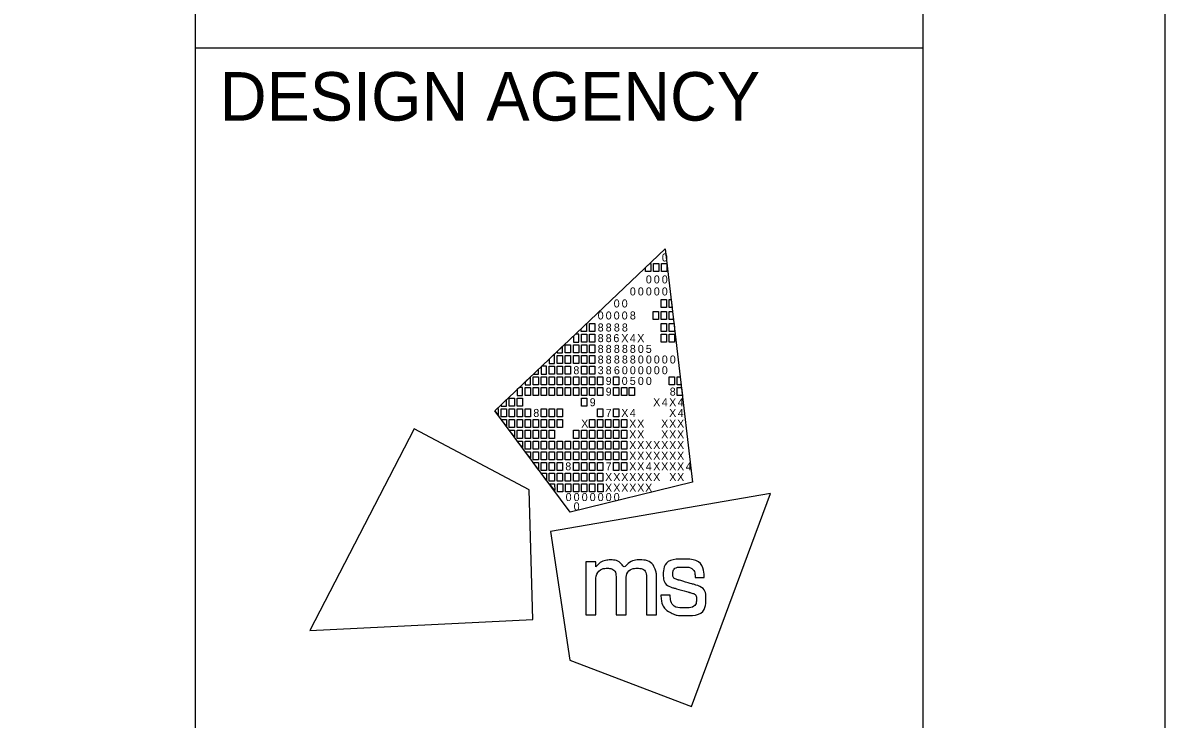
# Model space of a CAD drawing. Extents: x 0 to 34, y 0 to 22.
# Drawn here: x 31.644 to 34, y 3.616 to 5.052 of the extents above; entities that cross this region are included whole.
import ezdxf

# ---------------------------------------------------------------- set-up
doc = ezdxf.new("R2010")
doc.units = 0
for name, color, linetype in [('SH_Border', 7, 'Continuous'), ('SH_Cut_Line', 7, 'Continuous'), ('SH_Data', 7, 'Continuous')]:
    doc.layers.add(name, color=color, linetype=linetype)

msp = doc.modelspace()

# ---------------------------------------------------------------- linework, layer by layer
at = {"layer": 'SH_Border'}
for p, q in [((32, 0.5), (32, 21.5)), ((32, 5), (33.5, 5)), ((32.6175, 4.2519), (32.9688, 4.5861)), ((32.9688, 4.5861), (32.9688, 4.5861)), ((32.9688, 4.5861), (33.0253, 4.1052)), ((32.773, 4.043), (32.6175, 4.2519)), ((33.0253, 4.1052), (32.773, 4.043))]:
    msp.add_line(p, q, dxfattribs=at)
for points in [[(1.5, 21.5), (33.5, 21.5), (33.5, 0.5), (1.5, 0.5)], [(32.9279, 4.5472), (32.9369, 4.5558), (32.9389, 4.5558), (32.9389, 4.5393), (32.9279, 4.5393)], [(32.9444, 4.5558), (32.9554, 4.5558), (32.9554, 4.5393), (32.9444, 4.5393)], [(32.9609, 4.5558), (32.9719, 4.5558), (32.9719, 4.5393), (32.9609, 4.5393)], [(32.9606, 4.4815), (32.9716, 4.4815), (32.9716, 4.465), (32.9606, 4.465)], [(32.9771, 4.4815), (32.9811, 4.4815), (32.983, 4.465), (32.9771, 4.465)], [(32.9441, 4.4567), (32.9551, 4.4567), (32.9551, 4.4402), (32.9441, 4.4402)], [(32.9606, 4.4567), (32.9716, 4.4567), (32.9716, 4.4402), (32.9606, 4.4402)], [(32.9771, 4.4567), (32.984, 4.4567), (32.9859, 4.4402), (32.9771, 4.4402)], [(32.7953, 4.4211), (32.8064, 4.4316), (32.8064, 4.4154), (32.7953, 4.4154)], [(32.8123, 4.4319), (32.8233, 4.4319), (32.8233, 4.4154), (32.8123, 4.4154)], [(32.9606, 4.4319), (32.9716, 4.4319), (32.9716, 4.4154), (32.9606, 4.4154)], [(32.9771, 4.4319), (32.9869, 4.4319), (32.9881, 4.4218), (32.9881, 4.4154), (32.9771, 4.4154)], [(32.7958, 4.4099), (32.8068, 4.4099), (32.8068, 4.3934), (32.7958, 4.3934)], [(32.8123, 4.4099), (32.8233, 4.4099), (32.8233, 4.3934), (32.8123, 4.3934)], [(32.9606, 4.4099), (32.9716, 4.4099), (32.9716, 4.3934), (32.9606, 4.3934)], [(32.9771, 4.4099), (32.9881, 4.4099), (32.9881, 4.3934), (32.9771, 4.3934)], [(32.7627, 4.3879), (32.7737, 4.3879), (32.7737, 4.3714), (32.7627, 4.3714)], [(32.7793, 4.3879), (32.7903, 4.3879), (32.7903, 4.3714), (32.7793, 4.3714)], [(32.7958, 4.3879), (32.8068, 4.3879), (32.8068, 4.3714), (32.7958, 4.3714)], [(32.8123, 4.3879), (32.8233, 4.3879), (32.8233, 4.3714), (32.8123, 4.3714)], [(32.7462, 4.3659), (32.7572, 4.3659), (32.7572, 4.3494), (32.7462, 4.3494)], [(32.7627, 4.3659), (32.7737, 4.3659), (32.7737, 4.3494), (32.7627, 4.3494)], [(32.7793, 4.3659), (32.7903, 4.3659), (32.7903, 4.3494), (32.7793, 4.3494)], [(32.7958, 4.3659), (32.8068, 4.3659), (32.8068, 4.3494), (32.7958, 4.3494)], [(32.8123, 4.3659), (32.8233, 4.3659), (32.8233, 4.3494), (32.8123, 4.3494)], [(32.7297, 4.3439), (32.7407, 4.3439), (32.7407, 4.3273), (32.7297, 4.3273)], [(32.7462, 4.3439), (32.7572, 4.3439), (32.7572, 4.3273), (32.7462, 4.3273)], [(32.7627, 4.3439), (32.7737, 4.3439), (32.7737, 4.3273), (32.7627, 4.3273)], [(32.7958, 4.3439), (32.8068, 4.3439), (32.8068, 4.3273), (32.7958, 4.3273)], [(32.8123, 4.3439), (32.8233, 4.3439), (32.8233, 4.3273), (32.8123, 4.3273)], [(32.6967, 4.3218), (32.7077, 4.3218), (32.7077, 4.3053), (32.6967, 4.3053)], [(32.7132, 4.3218), (32.7242, 4.3218), (32.7242, 4.3053), (32.7132, 4.3053)], [(32.7297, 4.3218), (32.7407, 4.3218), (32.7407, 4.3053), (32.7297, 4.3053)], [(32.7462, 4.3218), (32.7572, 4.3218), (32.7572, 4.3053), (32.7462, 4.3053)], [(32.7627, 4.3218), (32.7737, 4.3218), (32.7737, 4.3053), (32.7627, 4.3053)], [(32.7793, 4.3218), (32.7903, 4.3218), (32.7903, 4.3053), (32.7793, 4.3053)], [(32.7958, 4.3218), (32.8068, 4.3218), (32.8068, 4.3053), (32.7958, 4.3053)], [(32.8123, 4.3218), (32.8233, 4.3218), (32.8233, 4.3053), (32.8123, 4.3053)], [(32.8288, 4.3218), (32.8398, 4.3218), (32.8398, 4.3053), (32.8288, 4.3053)], [(32.8618, 4.3218), (32.8728, 4.3218), (32.8728, 4.3053), (32.8618, 4.3053)], [(32.9771, 4.3218), (32.9881, 4.3218), (32.9881, 4.3053), (32.9771, 4.3053)], [(32.9935, 4.3218), (32.9998, 4.3218), (33.0018, 4.3053), (32.9935, 4.3053)], [(32.6802, 4.2998), (32.6912, 4.2998), (32.6912, 4.2833), (32.6802, 4.2833)], [(32.6967, 4.2998), (32.7077, 4.2998), (32.7077, 4.2833), (32.6967, 4.2833)], [(32.7132, 4.2998), (32.7242, 4.2998), (32.7242, 4.2833), (32.7132, 4.2833)], [(32.7297, 4.2998), (32.7407, 4.2998), (32.7407, 4.2833), (32.7297, 4.2833)], [(32.7462, 4.2998), (32.7572, 4.2998), (32.7572, 4.2833), (32.7462, 4.2833)], [(32.7627, 4.2998), (32.7737, 4.2998), (32.7737, 4.2833), (32.7627, 4.2833)], [(32.7793, 4.2998), (32.7903, 4.2998), (32.7903, 4.2833), (32.7793, 4.2833)], [(32.7958, 4.2998), (32.8068, 4.2998), (32.8068, 4.2833), (32.7958, 4.2833)], [(32.8123, 4.2998), (32.8233, 4.2998), (32.8233, 4.2833), (32.8123, 4.2833)], [(32.8288, 4.2998), (32.8398, 4.2998), (32.8398, 4.2833), (32.8288, 4.2833)], [(32.8618, 4.2998), (32.8728, 4.2998), (32.8728, 4.2833), (32.8618, 4.2833)], [(32.8783, 4.2998), (32.8893, 4.2998), (32.8893, 4.2833), (32.8783, 4.2833)], [(32.8947, 4.2998), (32.9057, 4.2998), (32.9057, 4.2833), (32.8947, 4.2833)], [(32.9935, 4.2998), (33.0024, 4.2998), (33.0044, 4.2833), (32.9935, 4.2833)], [(32.6471, 4.2778), (32.6581, 4.2778), (32.6581, 4.2613), (32.6471, 4.2613)], [(32.6637, 4.2778), (32.6747, 4.2778), (32.6747, 4.2613), (32.6637, 4.2613)], [(32.7958, 4.2778), (32.8068, 4.2778), (32.8068, 4.2613), (32.7958, 4.2613)], [(32.6306, 4.2558), (32.6416, 4.2558), (32.6416, 4.2393), (32.6306, 4.2393)], [(32.6471, 4.2558), (32.6581, 4.2558), (32.6581, 4.2393), (32.6471, 4.2393)], [(32.6637, 4.2558), (32.6747, 4.2558), (32.6747, 4.2393), (32.6637, 4.2393)], [(32.6802, 4.2558), (32.6912, 4.2558), (32.6912, 4.2393), (32.6802, 4.2393)], [(32.7132, 4.2558), (32.7242, 4.2558), (32.7242, 4.2393), (32.7132, 4.2393)], [(32.7297, 4.2558), (32.7407, 4.2558), (32.7407, 4.2393), (32.7297, 4.2393)], [(32.7462, 4.2558), (32.7572, 4.2558), (32.7572, 4.2393), (32.7462, 4.2393)], [(32.8288, 4.2558), (32.8398, 4.2558), (32.8398, 4.2393), (32.8288, 4.2393)], [(32.8618, 4.2558), (32.8728, 4.2558), (32.8728, 4.2393), (32.8618, 4.2393)], [(32.6306, 4.2338), (32.6416, 4.2338), (32.6416, 4.22)], [(32.6471, 4.2338), (32.6581, 4.2338), (32.6581, 4.2173), (32.6471, 4.2173)], [(32.6637, 4.2338), (32.6747, 4.2338), (32.6747, 4.2173), (32.6637, 4.2173)], [(32.6802, 4.2338), (32.6912, 4.2338), (32.6912, 4.2173), (32.6802, 4.2173)], [(32.6967, 4.2338), (32.7077, 4.2338), (32.7077, 4.2173), (32.6967, 4.2173)], [(32.7132, 4.2338), (32.7242, 4.2338), (32.7242, 4.2173), (32.7132, 4.2173)], [(32.7297, 4.2338), (32.7407, 4.2338), (32.7407, 4.2173), (32.7297, 4.2173)], [(32.7462, 4.2338), (32.7572, 4.2338), (32.7572, 4.2173), (32.7462, 4.2173)], [(32.8123, 4.2338), (32.8233, 4.2338), (32.8233, 4.2173), (32.8123, 4.2173)], [(32.8288, 4.2338), (32.8398, 4.2338), (32.8398, 4.2173), (32.8288, 4.2173)], [(32.8453, 4.2338), (32.8563, 4.2338), (32.8563, 4.2173), (32.8453, 4.2173)], [(32.8618, 4.2338), (32.8728, 4.2338), (32.8728, 4.2173), (32.8618, 4.2173)], [(32.8783, 4.2338), (32.8893, 4.2338), (32.8893, 4.2173), (32.8783, 4.2173)], [(32.6471, 4.2117), (32.6581, 4.2117), (32.6581, 4.198)], [(32.6637, 4.2117), (32.6747, 4.2117), (32.6747, 4.1952), (32.6637, 4.1952)], [(32.6802, 4.2117), (32.6912, 4.2117), (32.6912, 4.1952), (32.6802, 4.1952)], [(32.6967, 4.2117), (32.7077, 4.2117), (32.7077, 4.1952), (32.6967, 4.1952)], [(32.7132, 4.2117), (32.7242, 4.2117), (32.7242, 4.1952), (32.7132, 4.1952)], [(32.7297, 4.2117), (32.7407, 4.2117), (32.7407, 4.1952), (32.7297, 4.1952)], [(32.7793, 4.2117), (32.7903, 4.2117), (32.7903, 4.1952), (32.7793, 4.1952)], [(32.7958, 4.2117), (32.8068, 4.2117), (32.8068, 4.1952), (32.7958, 4.1952)], [(32.8123, 4.2117), (32.8233, 4.2117), (32.8233, 4.1952), (32.8123, 4.1952)], [(32.8288, 4.2117), (32.8398, 4.2117), (32.8398, 4.1952), (32.8288, 4.1952)], [(32.8453, 4.2117), (32.8563, 4.2117), (32.8563, 4.1952), (32.8453, 4.1952)], [(32.8618, 4.2117), (32.8728, 4.2117), (32.8728, 4.1952), (32.8618, 4.1952)], [(32.8783, 4.2117), (32.8893, 4.2117), (32.8893, 4.1952), (32.8783, 4.1952)], [(32.6637, 4.1897), (32.6747, 4.1897), (32.6747, 4.176)], [(32.6747, 4.1897), (32.6747, 4.1897), (32.6747, 4.1897)], [(32.6802, 4.1897), (32.6912, 4.1897), (32.6912, 4.1732), (32.6802, 4.1732)], [(32.6967, 4.1897), (32.7077, 4.1897), (32.7077, 4.1732), (32.6967, 4.1732)], [(32.7132, 4.1897), (32.7242, 4.1897), (32.7242, 4.1732), (32.7132, 4.1732)], [(32.7297, 4.1897), (32.7407, 4.1897), (32.7407, 4.1732), (32.7297, 4.1732)], [(32.7462, 4.1897), (32.7572, 4.1897), (32.7572, 4.1732), (32.7462, 4.1732)], [(32.7627, 4.1897), (32.7737, 4.1897), (32.7737, 4.1732), (32.7627, 4.1732)], [(32.7793, 4.1897), (32.7903, 4.1897), (32.7903, 4.1732), (32.7793, 4.1732)], [(32.7958, 4.1897), (32.8068, 4.1897), (32.8068, 4.1732), (32.7958, 4.1732)], [(32.8123, 4.1897), (32.8233, 4.1897), (32.8233, 4.1732), (32.8123, 4.1732)], [(32.8288, 4.1897), (32.8398, 4.1897), (32.8398, 4.1732), (32.8288, 4.1732)], [(32.8453, 4.1897), (32.8563, 4.1897), (32.8563, 4.1732), (32.8453, 4.1732)], [(32.8618, 4.1897), (32.8728, 4.1897), (32.8728, 4.1732), (32.8618, 4.1732)], [(32.8783, 4.1897), (32.8893, 4.1897), (32.8893, 4.1732), (32.8783, 4.1732)], [(32.6802, 4.1677), (32.6912, 4.1677), (32.6912, 4.154)], [(32.6967, 4.1677), (32.7077, 4.1677), (32.7077, 4.1512), (32.6967, 4.1512)], [(32.7132, 4.1677), (32.7242, 4.1677), (32.7242, 4.1512), (32.7132, 4.1512)], [(32.7297, 4.1677), (32.7407, 4.1677), (32.7407, 4.1512), (32.7297, 4.1512)], [(32.7462, 4.1677), (32.7572, 4.1677), (32.7572, 4.1512), (32.7462, 4.1512)], [(32.7627, 4.1677), (32.7737, 4.1677), (32.7737, 4.1512), (32.7627, 4.1512)], [(32.7793, 4.1677), (32.7903, 4.1677), (32.7903, 4.1512), (32.7793, 4.1512)], [(32.7958, 4.1677), (32.8068, 4.1677), (32.8068, 4.1512), (32.7958, 4.1512)], [(32.8123, 4.1677), (32.8233, 4.1677), (32.8233, 4.1512), (32.8123, 4.1512)], [(32.8288, 4.1677), (32.8398, 4.1677), (32.8398, 4.1512), (32.8288, 4.1512)], [(32.8453, 4.1677), (32.8563, 4.1677), (32.8563, 4.1512), (32.8453, 4.1512)], [(32.8618, 4.1677), (32.8728, 4.1677), (32.8728, 4.1512), (32.8618, 4.1512)], [(32.8783, 4.1677), (32.8893, 4.1677), (32.8893, 4.1512), (32.8783, 4.1512)], [(32.7077, 4.1305), (32.6965, 4.1457), (32.7077, 4.1457)], [(32.7132, 4.1457), (32.7242, 4.1457), (32.7242, 4.1292), (32.7132, 4.1292)], [(32.724, 4.1082), (32.7132, 4.1237), (32.7242, 4.1237)], [(32.7297, 4.1457), (32.7407, 4.1457), (32.7407, 4.1292), (32.7297, 4.1292)], [(32.7297, 4.1237), (32.7407, 4.1237), (32.7407, 4.1072), (32.7297, 4.1072)], [(32.7462, 4.1457), (32.7572, 4.1457), (32.7572, 4.1292), (32.7462, 4.1292)], [(32.7462, 4.1237), (32.7572, 4.1237), (32.7572, 4.1072), (32.7462, 4.1072)], [(32.7627, 4.1237), (32.7737, 4.1237), (32.7737, 4.1072), (32.7627, 4.1072)], [(32.7793, 4.1457), (32.7903, 4.1457), (32.7903, 4.1292), (32.7793, 4.1292)], [(32.7793, 4.1237), (32.7903, 4.1237), (32.7903, 4.1072), (32.7793, 4.1072)], [(32.7958, 4.1457), (32.8068, 4.1457), (32.8068, 4.1292), (32.7958, 4.1292)], [(32.7958, 4.1237), (32.8068, 4.1237), (32.8068, 4.1072), (32.7958, 4.1072)], [(32.8123, 4.1457), (32.8233, 4.1457), (32.8233, 4.1292), (32.8123, 4.1292)], [(32.8123, 4.1237), (32.8233, 4.1237), (32.8233, 4.1072), (32.8123, 4.1072)], [(32.8288, 4.1457), (32.8398, 4.1457), (32.8398, 4.1292), (32.8288, 4.1292)], [(32.8288, 4.1237), (32.8398, 4.1237), (32.8398, 4.1072), (32.8288, 4.1072)], [(32.8618, 4.1457), (32.8728, 4.1457), (32.8728, 4.1292), (32.8618, 4.1292)], [(32.8783, 4.1457), (32.8893, 4.1457), (32.8893, 4.1292), (32.8783, 4.1292)], [(32.7302, 4.1017), (32.7407, 4.1017), (32.7408, 4.0875)], [(32.7463, 4.1017), (32.7573, 4.1017), (32.7573, 4.0852), (32.7463, 4.0852)], [(32.763, 4.1017), (32.774, 4.1017), (32.774, 4.0852), (32.763, 4.0852)], [(32.7794, 4.1017), (32.7904, 4.1017), (32.7904, 4.0852), (32.7794, 4.0852)], [(32.796, 4.1017), (32.807, 4.1017), (32.807, 4.0852), (32.796, 4.0852)], [(32.8129, 4.1017), (32.8239, 4.1017), (32.8239, 4.0851), (32.8129, 4.0851)], [(32.8296, 4.1017), (32.8406, 4.1017), (32.8406, 4.0851), (32.8296, 4.0851)]]:
    msp.add_lwpolyline(points, close=True, dxfattribs=at)
for points in [[(32.7903, 4.4099), (32.7836, 4.4099), (32.7793, 4.4058), (32.7793, 4.3934), (32.7903, 4.3934), (32.7903, 4.4099)], [(32.7572, 4.3849), (32.7462, 4.3744), (32.7462, 4.3714), (32.7572, 4.3714), (32.7572, 4.3849)], [(32.7407, 4.3691), (32.7297, 4.3587), (32.7297, 4.3494), (32.7407, 4.3494), (32.7407, 4.3691)], [(32.7077, 4.3377), (32.6968, 4.3273), (32.7077, 4.3273), (32.7077, 4.3377)], [(32.7242, 4.3439), (32.7141, 4.3439), (32.7132, 4.343), (32.7132, 4.3273), (32.7242, 4.3273), (32.7242, 4.3439)], [(32.6912, 4.322), (32.6802, 4.3115), (32.6802, 4.3053), (32.6912, 4.3053), (32.6912, 4.322)], [(32.6747, 4.2998), (32.6679, 4.2998), (32.6637, 4.2958), (32.6637, 4.2833), (32.6747, 4.2833), (32.6747, 4.2998)], [(32.6416, 4.2749), (32.6306, 4.2644), (32.6306, 4.2613), (32.6416, 4.2613), (32.6416, 4.2749)], [(32.6251, 4.2558), (32.6216, 4.2558), (32.6175, 4.2519), (32.6251, 4.2417), (32.6251, 4.2558)], [(32.4512, 4.2149), (32.2359, 3.7988), (32.6956, 3.8215), (32.6884, 4.0892), (32.4512, 4.2149)], [(33.0229, 3.6422), (33.1859, 4.0814), (32.7324, 4.0029), (32.7722, 3.7381), (33.0229, 3.6422)]]:
    msp.add_lwpolyline(points, dxfattribs=at)
for points in [[(32.8048, 3.8315), (32.8048, 3.8315), (32.8048, 3.9409), (32.8048, 3.9409), (32.8048, 3.9409), (32.8255, 3.9409), (32.8255, 3.9409), (32.8255, 3.9409), (32.8255, 3.9297), (32.8255, 3.9297), (32.8346, 3.9399), (32.8457, 3.9445), (32.8555, 3.9445), (32.8688, 3.9445), (32.8791, 3.9372), (32.8837, 3.9266), (32.8915, 3.9381), (32.905, 3.9446), (32.9166, 3.9446), (32.9325, 3.9446), (32.9451, 3.935), (32.9494, 3.9213), (32.9494, 3.9212), (32.9494, 3.9212), (32.9494, 3.9212), (32.9501, 3.919), (32.9506, 3.9172), (32.9506, 3.9071), (32.9506, 3.9071), (32.9506, 3.8314), (32.9506, 3.8314), (32.9506, 3.8314), (32.9303, 3.8314), (32.9303, 3.8314), (32.9303, 3.8314), (32.9303, 3.9048), (32.9303, 3.9048), (32.9303, 3.9201), (32.9219, 3.9274), (32.911, 3.9274), (32.8995, 3.9274), (32.8879, 3.9171), (32.8879, 3.9001), (32.8879, 3.9001), (32.8879, 3.8315), (32.8879, 3.8315), (32.8879, 3.8315), (32.8674, 3.8315), (32.8674, 3.8315), (32.8674, 3.8315), (32.8674, 3.9059), (32.8674, 3.9059), (32.8674, 3.9203), (32.8588, 3.9274), (32.8496, 3.9274), (32.8384, 3.9274), (32.8254, 3.917), (32.8254, 3.8962), (32.8254, 3.8962), (32.8254, 3.8315), (32.8254, 3.8315), (32.8254, 3.8315), (32.8048, 3.8315), (32.8048, 3.8315)], [(32.9595, 3.8709), (32.9595, 3.8709), (32.9595, 3.8717), (32.9595, 3.8717), (32.9595, 3.8717), (32.9603, 3.8717), (32.9603, 3.8717), (32.9603, 3.8717), (32.9783, 3.8717), (32.9783, 3.8717), (32.9783, 3.8717), (32.9789, 3.8717), (32.9789, 3.8717), (32.9789, 3.8717), (32.979, 3.871), (32.979, 3.871), (32.9803, 3.8554), (32.9887, 3.846), (33.009, 3.846), (33.0273, 3.846), (33.0333, 3.8554), (33.0333, 3.8631), (33.0333, 3.8732), (33.0256, 3.8758), (33.0175, 3.878), (33.0175, 3.878), (32.987, 3.8867), (32.987, 3.8867), (32.972, 3.8909), (32.9648, 3.9019), (32.9648, 3.9142), (32.9648, 3.9303), (32.9768, 3.9462), (33.0052, 3.9462), (33.0348, 3.9462), (33.0489, 3.9285), (33.0489, 3.9095), (33.0489, 3.9095), (33.0489, 3.9087), (33.0489, 3.9087), (33.0489, 3.9087), (33.0482, 3.9087), (33.0482, 3.9087), (33.0482, 3.9087), (33.0312, 3.9087), (33.0312, 3.9087), (33.0312, 3.9087), (33.0305, 3.9087), (33.0305, 3.9087), (33.0305, 3.9087), (33.0305, 3.9094), (33.0305, 3.9094), (33.0301, 3.9208), (33.0226, 3.93), (33.0056, 3.93), (32.9891, 3.93), (32.9843, 3.9218), (32.9843, 3.9157), (32.9843, 3.9108), (32.9869, 3.9059), (32.9959, 3.9033), (32.9959, 3.9033), (33.0255, 3.8948), (33.0255, 3.8948), (33.0462, 3.8889), (33.0527, 3.8777), (33.0527, 3.8639), (33.0527, 3.8462), (33.041, 3.8298), (33.0087, 3.8298), (32.9952, 3.8298), (32.9877, 3.8321), (32.9823, 3.8348), (32.969, 3.8414), (32.9609, 3.8536), (32.9595, 3.8709)]]:
    msp.add_open_spline(points, degree=3, dxfattribs=at)
at = {"layer": 'SH_Cut_Line'}
msp.add_lwpolyline([(0, 0), (34, 0), (34, 22), (0, 22)], close=True, dxfattribs=at)
at = {"layer": 'SH_Data'}
msp.add_line((32.75, 4), (32.75, 4), dxfattribs=at)

# ---------------------------------------------------------------- texts
at = {"layer": 'SH_Border'}
for s, p in [('0', (32.9617, 4.5597)), ('0', (32.9288, 4.5145)), ('0', (32.9452, 4.5145)), ('0', (32.9617, 4.5145)), ('0', (32.8958, 4.4897)), ('0', (32.9123, 4.4897)), ('0', (32.9288, 4.4897)), ('0', (32.9452, 4.4897)), ('0', (32.9617, 4.4897)), ('0', (32.8625, 4.465)), ('0', (32.879, 4.465)), ('0', (32.8295, 4.4402)), ('0', (32.846, 4.4402)), ('0', (32.8625, 4.4402)), ('0', (32.879, 4.4402)), ('8', (32.8958, 4.4402)), ('8', (32.8295, 4.4154)), ('8', (32.846, 4.4154)), ('8', (32.8628, 4.4154)), ('8', (32.8793, 4.4154)), ('8', (32.8295, 4.3934)), ('8', (32.846, 4.3934)), ('6', (32.8618, 4.3934)), ('X', (32.8781, 4.3934)), ('4', (32.8958, 4.3934)), ('X', (32.911, 4.3934)), ('8', (32.8295, 4.3713)), ('8', (32.846, 4.3713)), ('8', (32.8628, 4.3713)), ('8', (32.8794, 4.3713)), ('8', (32.8958, 4.3713)), ('0', (32.9123, 4.3713)), ('5', (32.9287, 4.3713)), ('8', (32.8295, 4.3494)), ('8', (32.846, 4.3494)), ('8', (32.8628, 4.3494)), ('8', (32.8794, 4.3494)), ('8', (32.8958, 4.3494)), ('0', (32.9123, 4.3494)), ('0', (32.9288, 4.3494)), ('0', (32.9452, 4.3494)), ('0', (32.9617, 4.3494)), ('0', (32.9782, 4.3494)), ('8', (32.7793, 4.3273)), ('3', (32.8295, 4.3273)), ('8', (32.846, 4.3273)), ('6', (32.8629, 4.3273)), ('0', (32.8793, 4.3273)), ('0', (32.8958, 4.3273)), ('0', (32.9123, 4.3273)), ('0', (32.9288, 4.3273)), ('0', (32.9452, 4.3273)), ('0', (32.9617, 4.3273)), ('9', (32.846, 4.3053)), ('0', (32.879, 4.3053)), ('5', (32.8957, 4.3053)), ('0', (32.9123, 4.3053)), ('0', (32.9288, 4.3053)), ('9', (32.846, 4.2833)), ('8', (32.9781, 4.2833)), ('9', (32.813, 4.2613)), ('X', (32.9439, 4.2613)), ('4', (32.9617, 4.2613)), ('X', (32.9769, 4.2613)), ('4', (32.9946, 4.2613)), ('8', (32.6967, 4.2393)), ('7', (32.846, 4.2393)), ('X', (32.8781, 4.2393)), ('4', (32.8958, 4.2393)), ('X', (32.9769, 4.2393)), ('4', (32.9946, 4.2393)), ('X', (32.7955, 4.2173)), ('X', (32.8945, 4.2173)), ('X', (32.911, 4.2173)), ('X', (32.9604, 4.2173)), ('X', (32.9769, 4.2173)), ('X', (32.9933, 4.2173)), ('X', (32.8945, 4.1952)), ('X', (32.911, 4.1952)), ('X', (32.9604, 4.1952)), ('X', (32.9769, 4.1952)), ('X', (32.9933, 4.1952)), ('X', (32.8945, 4.1732)), ('X', (32.911, 4.1732)), ('X', (32.9274, 4.1732)), ('X', (32.9439, 4.1732)), ('X', (32.9604, 4.1732)), ('X', (32.9769, 4.1732)), ('X', (32.9933, 4.1732)), ('X', (32.8945, 4.1512)), ('X', (32.911, 4.1512)), ('X', (32.9274, 4.1512)), ('X', (32.9439, 4.1512)), ('X', (32.9604, 4.1512)), ('X', (32.9769, 4.1512)), ('X', (32.9933, 4.1512)), ('8', (32.7627, 4.1292)), ('X', (32.8447, 4.1072)), ('7', (32.846, 4.1292)), ('X', (32.8616, 4.1072)), ('X', (32.878, 4.1072)), ('X', (32.8945, 4.1292)), ('X', (32.8945, 4.1072)), ('X', (32.911, 4.1292)), ('X', (32.911, 4.1072)), ('X', (32.9274, 4.1072)), ('4', (32.9288, 4.1292)), ('X', (32.9439, 4.1292)), ('X', (32.9439, 4.1072)), ('X', (32.9604, 4.1292)), ('X', (32.9769, 4.1292)), ('X', (32.9771, 4.1072)), ('X', (32.9933, 4.1292)), ('X', (32.9933, 4.1072)), ('4', (33.0111, 4.1292)), ('X', (32.8447, 4.0851)), ('X', (32.8616, 4.0851)), ('X', (32.878, 4.0851)), ('X', (32.8945, 4.0851)), ('X', (32.911, 4.0851)), ('X', (32.9274, 4.0851)), ('0', (32.7634, 4.0659)), ('0', (32.7799, 4.0659)), ('0', (32.7965, 4.0659)), ('0', (32.813, 4.0659)), ('0', (32.8295, 4.0659)), ('0', (32.846, 4.0659)), ('0', (32.8625, 4.0659)), ('0', (32.7799, 4.0467))]:
    msp.add_text(s, height=0.0165, rotation=360, dxfattribs=at).set_placement(p)
at = {"layer": 'SH_Data'}
msp.add_text('DESIGN AGENCY', height=0.1, dxfattribs=at).set_placement((32.05, 4.85))

doc.saveas('drawing.dxf')
